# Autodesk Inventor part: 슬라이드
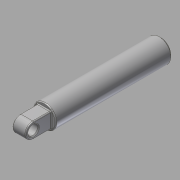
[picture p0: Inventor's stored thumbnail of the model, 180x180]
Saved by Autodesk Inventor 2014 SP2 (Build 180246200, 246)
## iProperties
Created: 2016-02
Part Number: 슬라이드
Material: 강철, 연강
Document SubType Name: Modeling
Designer: test
Density: 1 g/cm^3
Appearance: 강철
Author: test
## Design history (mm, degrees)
sketch "스케치2"
  geometry: C1 r 6 at (0, 0); 1 further point
  constraints: 1 centre point, 1 coincident
  dimensions: "d0" = 12 diameter of C1
extrude "돌출1" new body sketch "스케치2" distance "d1" = 60; taper "d2" = 0 deg
hole "구멍1" diameter "d5" = 5.917; stored, may be unused: countersink angle "d9" = 90 deg, drill point angle "d11" = 118 deg; dims "d3" = 10, "d4" = 10, "d6" = 10, "d7" = 4, "d8" = 2, "d10" = 12
chamfer "모따기1" distance "d12" = 1; stored, may be unused: second distance "d13" = 2, angle "d14" = 45 deg
sketch "스케치3"
  geometry: L1 (0, 6)-(0, -6) reference; L2 (0, 4)-(-9, 4); L3 (-9, -4)-(0, -4); L4 (0, -4)-(0, 4); C1 r 2.5 at (-9, 0); A1 r 4 centre (-9, 0) between (-9, 4) and (-9, -4); 2 further points
  constraints: 6 end point, 2 centre point, 2 point on circle, 2 tangent, 1 coincident, 1 horizontal, 1 horizontal alignment, 1 midpoint, 1 parallel, 1 point on line, 1 vertical
  dimensions: "d15" = 13 dimension on A1 L1; "d16" = 8 distance between parallel lines of L3 L2; "d17" = 5 diameter of C1
extrude "돌출2" join sketch "스케치3" stored distance "d18" = 7; taper "d19" = 0 deg
chamfer "모따기2" distance "d20" = 0.5; stored, may be unused: second distance "d21" = 2, angle "d22" = 45 deg
fillet "모깎기1" dims "d23" = 0.5
fillet "모깎기2" dims "d24" = 0.5
fillet "모깎기3" dims "d25" = 0.5
node "솔리드1"
